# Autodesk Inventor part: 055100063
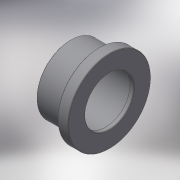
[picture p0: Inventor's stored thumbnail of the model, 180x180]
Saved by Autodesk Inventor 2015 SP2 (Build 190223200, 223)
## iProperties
Created: 2017-10
Part Number: 055100063
Material: Generic
Description: PLASSON FLANGE FLAT AD.-CEM 63
Document SubType Name: Modeling
Designer: KIM
Mass: 76.2916 g
Surface Area: 255.946 cm^2
Volume: 76.2916 cm^3
Density: 1 g/cm^3
Appearance: Default
Author: KIM
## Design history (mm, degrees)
derived "055100.ipt"
feature "Solid1::055100.ipt"
tag "TaggingFeature1"
body "Solid1"
other parameters: "d0" = 41, "d1" = 76, "d2" = 63, "d3" = 56.7, "d4" = 9, "d5" = 38, "d8" = 0.63, "d_" = 63, "E_" = 76, "l_" = 38, "B_" = 9, "H_" = 41
